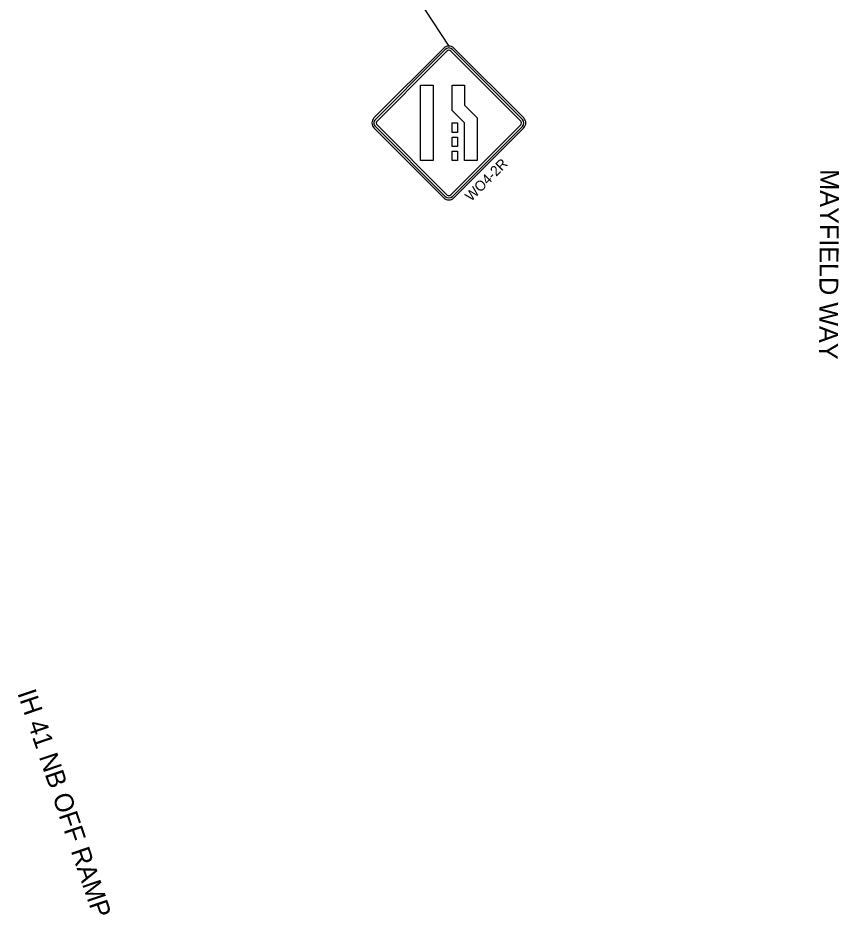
# Model space of a CAD drawing. Extents: x 358662 to 361839, y 132407 to 133741.
# Drawn here: x 359606.8 to 360042.9, y 132457.7 to 132934 of the extents above; entities that cross this region are included whole.
import ezdxf

# ---------------------------------------------------------------- set-up
doc = ezdxf.new("R2010")
doc.units = 0
doc.layers.add('E_MISCPROP_ShtDash', color=7, linetype='Continuous')
doc.layers.add('P_FTMS_LaneLbl', color=7, linetype='Continuous')

msp = doc.modelspace()

# ---------------------------------------------------------------- linework, layer by layer
at = {"layer": 'E_MISCPROP_ShtDash'}
for p, q in [((359820.69, 132858.24), (359820.69, 132898.24)), ((359820.69, 132898.24), (359827.36, 132898.24)), ((359827.36, 132898.24), (359827.36, 132858.24)), ((359837.36, 132884.9), (359837.36, 132898.24)), ((359837.36, 132898.24), (359844.02, 132898.24)), ((359844.02, 132898.24), (359844.02, 132887.67)), ((359844.03, 132887.67), (359850.66, 132881.03)), ((359844.02, 132878.24), (359837.36, 132884.9)), ((359837.25, 132878.24), (359840.27, 132878.24)), ((359837.36, 132873.24), (359837.36, 132878.24)), ((359840.27, 132878.24), (359840.27, 132873.24)), ((359844.02, 132858.24), (359844.02, 132878.24)), ((359850.69, 132880.91), (359850.69, 132858.24)), ((359840.27, 132873.24), (359837.36, 132873.24)), ((359837.36, 132865.74), (359837.36, 132870.74)), ((359837.36, 132870.74), (359840.27, 132870.74)), ((359840.27, 132870.74), (359840.27, 132865.74)), ((359840.27, 132865.74), (359837.36, 132865.74)), ((359837.36, 132858.24), (359837.36, 132863.24)), ((359837.36, 132863.24), (359840.27, 132863.24)), ((359840.27, 132863.24), (359840.27, 132858.24)), ((359827.36, 132858.24), (359820.69, 132858.24)), ((359840.27, 132858.24), (359837.36, 132858.24)), ((359850.69, 132858.24), (359844.02, 132858.24))]:
    msp.add_line(p, q, dxfattribs=at)
for points in [[(359795.92, 132880.89), (359833.04, 132918.01)], [(359828.19, 132909.92), (359834.66, 132916.39)], [(359829.62, 132913.12), (359833.78, 132917.28)], [(359836.72, 132916.39), (359873.85, 132879.27)], [(359837.61, 132917.28), (359874.73, 132880.15)], [(359838.34, 132918.01), (359875.47, 132880.89)], [(359796.65, 132880.15), (359829.78, 132913.28)], [(359797.54, 132879.27), (359828.3, 132910.03)], [(359833.04, 132838.46), (359795.92, 132875.59)], [(359833.78, 132839.2), (359796.65, 132876.32)], [(359834.84, 132839.9), (359797.54, 132877.21)], [(359873.85, 132877.21), (359836.72, 132840.08)], [(359874.73, 132876.32), (359837.61, 132839.2)], [(359875.47, 132875.59), (359838.34, 132838.46)]]:
    msp.add_lwpolyline(points, dxfattribs=at)
for centre, radius, start, end in [((359835.69, 132915.36), 3.75, 45, 135), ((359835.69, 132915.36), 2.71, 45, 135), ((359835.69, 132915.36), 1.46, 45, 135), ((359798.57, 132878.24), 3.75, 134.9981, 225), ((359798.57, 132878.24), 2.71, 134.9989, 225), ((359798.57, 132878.24), 1.46, 134.998, 224.9982), ((359872.81, 132878.24), 1.46, 315.0011, 45), ((359872.81, 132878.24), 2.71, 315, 45), ((359872.81, 132878.24), 3.75, 315, 45), ((359835.69, 132841.12), 1.46, 235.1509, 315.0019), ((359835.69, 132841.12), 3.75, 225, 315), ((359835.69, 132841.12), 2.71, 225, 315), ((359835.69, 132841.12), 1.46, 285.4294, 287.4573), ((359835.69, 132841.12), 1.46, 287.4573, 288.8574)]:
    msp.add_arc(centre, radius, start, end, dxfattribs=at)
at = {"layer": 'P_FTMS_LaneLbl'}
msp.add_line((359808.73, 132960.03), (359835.69, 132919.11), dxfattribs=at)

# ---------------------------------------------------------------- texts
at = {"layer": 'E_MISCPROP_ShtDash'}
msp.add_text('WO4-2R', height=5.4, rotation=45, dxfattribs=at).set_placement((359847.54, 132836.27))
at = {"layer": 'P_FTMS_LaneLbl'}
for s, rotation, p in [('MAYFIELD WAY', 269.6096, (360032.93, 132853.69)), ('IH 41 NB OFF RAMP', 288.7277, (359606.43, 132575.57))]:
    msp.add_text(s, height=10, rotation=rotation, dxfattribs=at).set_placement(p)

doc.saveas('drawing.dxf')
